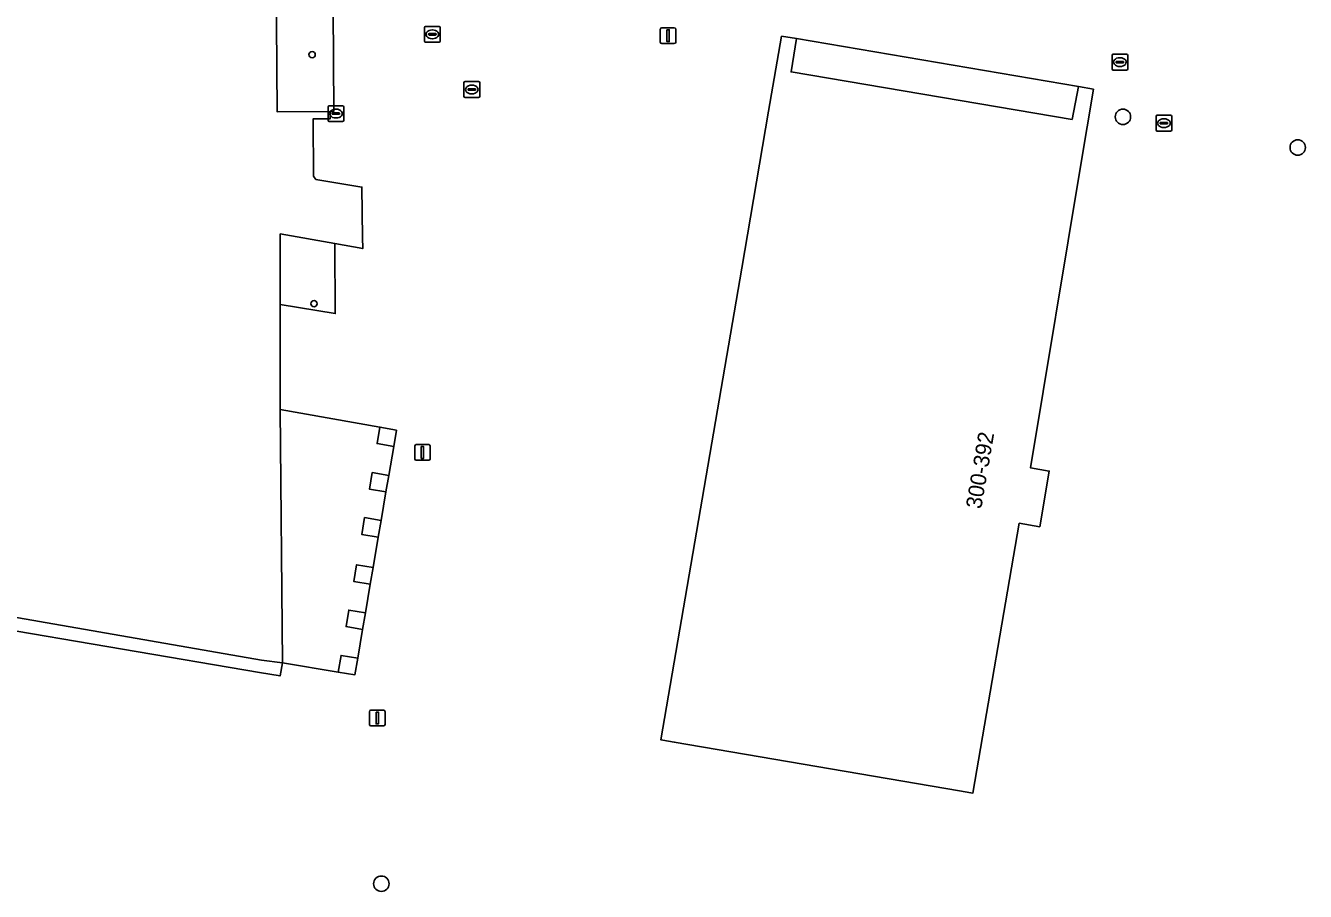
# Model space of a CAD drawing. Extents: x 161258 to 161838, y 380833 to 381727.
# Drawn here: x 161418.1 to 161499.4, y 380907.4 to 380962.4 of the extents above; entities that cross this region are included whole.
import ezdxf

# ---------------------------------------------------------------- set-up
doc = ezdxf.new("R2010")
doc.units = 0
for name, color, linetype in [('IMGEO_Boom', 7, 'Continuous'), ('IMGEO_Brandkraan', 7, 'Continuous'), ('IMGEO_Erf', 7, 'Continuous'), ('IMGEO_Kolk', 7, 'Continuous'), ('IMGEO_Lichtmast', 7, 'Continuous'), ('IMGEO_Pand', 7, 'Continuous'), ('IMGEO_Pand_nummerreeks', 7, 'Continuous'), ('IMGEO_Pand_overbouw', 7, 'Continuous'), ('IMGEO_Rioolput', 7, 'Continuous')]:
    doc.layers.add(name, color=color, linetype=linetype)

msp = doc.modelspace()

# ---------------------------------------------------------------- linework, layer by layer
at = {"layer": 'IMGEO_Boom'}
for centre in [(161487.848, 380956.64), (161498.947, 380954.694), (161440.743, 380907.913)]:
    msp.add_circle(centre, 0.489, dxfattribs=at)
at = {"layer": 'IMGEO_Brandkraan'}
for p, q in [((161437.356, 380956.423), (161437.356, 380957.275)), ((161437.431, 380957.349), (161438.283, 380957.349)), ((161437.844, 380957.129), (161437.869, 380957.129)), ((161438.357, 380957.275), (161438.357, 380956.423)), ((161438.283, 380956.349), (161437.431, 380956.349)), ((161437.615, 380956.843), (161437.615, 380956.855)), ((161438.053, 380956.806), (161437.655, 380956.806)), ((161437.658, 380956.892), (161438.056, 380956.892)), ((161437.867, 380956.569), (161437.842, 380956.569)), ((161438.099, 380956.855), (161438.099, 380956.843))]:
    msp.add_line(p, q, dxfattribs=at)
for points in [[(161437.356, 380956.423), (161437.356, 380957.275)], [(161437.431, 380957.349), (161438.283, 380957.349)], [(161438.357, 380957.275), (161438.357, 380956.423)], [(161438.283, 380956.349), (161437.431, 380956.349)]]:
    msp.add_lwpolyline(points, dxfattribs=at)
for centre, radius, start, end in [((161437.433, 380957.273), 0.0765, 91.55205, 178.44795), ((161437.433, 380957.273), 0.0765, 91.55205, 178.44795), ((161438.281, 380957.273), 0.0765, 1.55205, 88.44795), ((161438.281, 380957.273), 0.0765, 1.55205, 88.44795), ((161437.433, 380956.425), 0.0765, 181.55205, 268.44795), ((161437.433, 380956.425), 0.0765, 181.55205, 268.44795), ((161437.655, 380956.852), 0.0403, 85.87752, 175.75265), ((161437.652, 380956.842), 0.0366, 178.93798, 274.71019), ((161438.056, 380956.849), 0.043, 264.86636, 352.45326), ((161438.06, 380956.854), 0.0386, 1.73085, 96.63898), ((161438.281, 380956.425), 0.0765, 271.55205, 358.44795), ((161438.281, 380956.425), 0.0765, 271.55205, 358.44795)]:
    msp.add_arc(centre, radius, start, end, dxfattribs=at)
for centre, major_axis, ratio, start_param, end_param in [((161437.843, 380956.849), (-0.387, 0.002), 0.722429, 4.712389, 7.853982), ((161437.868, 380956.849), (-0.39, 0.002), 0.717154, 1.570796, 4.712389)]:
    msp.add_ellipse(centre, major_axis=major_axis, ratio=ratio, start_param=start_param, end_param=end_param, dxfattribs=at)
at = {"layer": 'IMGEO_Erf'}
msp.add_lwpolyline([(161434.023, 380971.148), (161434.118, 380956.967), (161437.5, 380956.974), (161437.502, 380956.514), (161436.409, 380956.509), (161436.437, 380952.87), (161436.585, 380952.666), (161439.506, 380952.173), (161439.552, 380948.973), (161439.562, 380948.274), (161437.785, 380948.589), (161434.324, 380949.202), (161434.323, 380944.725), (161434.322, 380938.038), (161434.454, 380921.951), (161433.132, 380922.125), (161415.724, 380925.137)], dxfattribs=at)
for points in [[(161467.112, 380961.61), (161466.768, 380959.497), (161484.617, 380956.479), (161485.016, 380958.571), (161485.967, 380958.39), (161485.177, 380953.62), (161481.981, 380934.334), (161483.164, 380934.132), (161482.561, 380930.592), (161481.259, 380930.814), (161478.315, 380913.67), (161478.183, 380913.693), (161477.473, 380913.814), (161459.352, 380916.915), (161458.632, 380917.038), (161458.494, 380917.062), (161463.634, 380947.032), (161464.19, 380950.274), (161465.344, 380957.003), (161466.161, 380961.765)], [(161441.705, 380936.736), (161441.53, 380935.695), (161440.475, 380935.875), (161440.653, 380936.922)], [(161441.213, 380933.859), (161441.033, 380932.805), (161439.984, 380932.983), (161440.163, 380934.037)], [(161440.732, 380930.994), (161440.548, 380929.927), (161439.495, 380930.106), (161439.676, 380931.173)], [(161440.22, 380928.004), (161440.04, 380926.947), (161438.988, 380927.125), (161439.167, 380928.182)], [(161439.733, 380925.118), (161439.554, 380924.066), (161438.498, 380924.246), (161438.677, 380925.298)], [(161439.242, 380922.245), (161439.063, 380921.191), (161438.009, 380921.364), (161438.189, 380922.424)]]:
    msp.add_lwpolyline(points, close=True, dxfattribs=at)
for centre, start, end in [((161436.347, 380960.592), 90, 270), ((161436.347, 380960.592), 270, 90), ((161436.468, 380944.767), 90, 270), ((161436.468, 380944.767), 270, 90)]:
    msp.add_arc(centre, 0.2, start, end, dxfattribs=at)
at = {"layer": 'IMGEO_Kolk'}
for p, q in [((161443.479, 380961.457), (161443.479, 380962.309)), ((161443.554, 380962.383), (161444.406, 380962.383)), ((161443.738, 380961.877), (161443.738, 380961.889)), ((161444.176, 380961.84), (161443.778, 380961.84)), ((161443.781, 380961.926), (161444.179, 380961.926)), ((161443.967, 380962.163), (161443.992, 380962.163)), ((161444.222, 380961.889), (161444.222, 380961.877)), ((161444.48, 380962.309), (161444.48, 380961.457)), ((161444.406, 380961.383), (161443.554, 380961.383)), ((161443.99, 380961.603), (161443.965, 380961.603)), ((161487.152, 380959.689), (161487.152, 380960.541)), ((161487.227, 380960.615), (161488.079, 380960.615)), ((161487.64, 380960.395), (161487.665, 380960.395)), ((161488.153, 380960.541), (161488.153, 380959.689)), ((161488.079, 380959.615), (161487.227, 380959.615)), ((161487.411, 380960.109), (161487.411, 380960.121)), ((161487.849, 380960.072), (161487.451, 380960.072)), ((161487.454, 380960.158), (161487.852, 380960.158)), ((161487.663, 380959.835), (161487.638, 380959.835)), ((161487.895, 380960.121), (161487.895, 380960.109))]:
    msp.add_line(p, q, dxfattribs=at)
for points in [[(161443.479, 380961.457), (161443.479, 380962.309)], [(161443.554, 380962.383), (161444.406, 380962.383)], [(161444.48, 380962.309), (161444.48, 380961.457)], [(161444.406, 380961.383), (161443.554, 380961.383)], [(161487.152, 380959.689), (161487.152, 380960.541)], [(161487.227, 380960.615), (161488.079, 380960.615)], [(161488.153, 380960.541), (161488.153, 380959.689)], [(161488.079, 380959.615), (161487.227, 380959.615)]]:
    msp.add_lwpolyline(points, dxfattribs=at)
for centre, radius, start, end in [((161443.556, 380962.307), 0.0765, 91.55205, 178.44795), ((161443.556, 380962.307), 0.0765, 91.55205, 178.44795), ((161443.778, 380961.886), 0.0403, 85.87752, 175.75265), ((161443.775, 380961.876), 0.0366, 178.93798, 274.71019), ((161444.179, 380961.883), 0.043, 264.86636, 352.45326), ((161444.183, 380961.888), 0.0386, 1.73085, 96.63898), ((161444.404, 380962.307), 0.0765, 1.55205, 88.44795), ((161444.404, 380962.307), 0.0765, 1.55205, 88.44795), ((161443.556, 380961.459), 0.0765, 181.55205, 268.44795), ((161443.556, 380961.459), 0.0765, 181.55205, 268.44795), ((161444.404, 380961.459), 0.0765, 271.55205, 358.44795), ((161444.404, 380961.459), 0.0765, 271.55205, 358.44795), ((161487.229, 380960.539), 0.0765, 91.55205, 178.44795), ((161487.229, 380960.539), 0.0765, 91.55205, 178.44795), ((161488.077, 380960.539), 0.0765, 1.55205, 88.44795), ((161488.077, 380960.539), 0.0765, 1.55205, 88.44795), ((161487.229, 380959.691), 0.0765, 181.55205, 268.44795), ((161487.229, 380959.691), 0.0765, 181.55205, 268.44795), ((161487.451, 380960.118), 0.0403, 85.87752, 175.75265), ((161487.448, 380960.108), 0.0366, 178.93798, 274.71019), ((161487.852, 380960.115), 0.043, 264.86636, 352.45326), ((161487.856, 380960.12), 0.0386, 1.73085, 96.63898), ((161488.077, 380959.691), 0.0765, 271.55205, 358.44795), ((161488.077, 380959.691), 0.0765, 271.55205, 358.44795)]:
    msp.add_arc(centre, radius, start, end, dxfattribs=at)
for centre, major_axis, ratio, start_param, end_param in [((161443.966, 380961.883), (-0.387, 0.002), 0.722429, 4.712389, 7.853982), ((161443.991, 380961.883), (-0.39, 0.002), 0.717154, 1.570796, 4.712389), ((161487.639, 380960.115), (-0.387, 0.002), 0.722429, 4.712389, 7.853982), ((161487.664, 380960.115), (-0.39, 0.002), 0.717154, 1.570796, 4.712389)]:
    msp.add_ellipse(centre, major_axis=major_axis, ratio=ratio, start_param=start_param, end_param=end_param, dxfattribs=at)
at = {"layer": 'IMGEO_Lichtmast'}
for p, q in [((161458.456, 380961.395), (161458.456, 380962.195)), ((161458.456, 380962.195), (161458.456, 380961.395)), ((161458.556, 380962.295), (161459.346, 380962.295)), ((161459.346, 380962.295), (161458.556, 380962.295)), ((161459.446, 380962.195), (161459.446, 380961.395)), ((161459.446, 380961.395), (161459.446, 380962.195)), ((161459.346, 380961.295), (161458.556, 380961.295)), ((161458.556, 380961.295), (161459.346, 380961.295)), ((161442.959, 380935.815), (161443.749, 380935.815)), ((161443.749, 380935.815), (161442.959, 380935.815)), ((161442.859, 380934.915), (161442.859, 380935.715)), ((161442.859, 380935.715), (161442.859, 380934.915)), ((161443.849, 380935.715), (161443.849, 380934.915)), ((161443.849, 380934.915), (161443.849, 380935.715)), ((161443.749, 380934.815), (161442.959, 380934.815)), ((161442.959, 380934.815), (161443.749, 380934.815)), ((161439.985, 380918.039), (161439.985, 380918.839)), ((161439.985, 380918.839), (161439.985, 380918.039)), ((161440.085, 380918.939), (161440.875, 380918.939)), ((161440.875, 380918.939), (161440.085, 380918.939)), ((161440.975, 380918.839), (161440.975, 380918.039)), ((161440.975, 380918.039), (161440.975, 380918.839)), ((161440.875, 380917.939), (161440.085, 380917.939)), ((161440.085, 380917.939), (161440.875, 380917.939))]:
    msp.add_line(p, q, dxfattribs=at)
for points in [[(161458.876, 380962.17), (161459.026, 380962.17), (161459.026, 380961.42), (161458.876, 380961.42), (161458.876, 380962.17)], [(161443.279, 380935.69), (161443.429, 380935.69), (161443.429, 380934.94), (161443.279, 380934.94), (161443.279, 380935.69)], [(161440.405, 380918.814), (161440.555, 380918.814), (161440.555, 380918.064), (161440.405, 380918.064), (161440.405, 380918.814)]]:
    msp.add_lwpolyline(points, dxfattribs=at)
for centre, start, end in [((161458.556, 380962.195), 90, 180), ((161458.556, 380962.195), 90, 180), ((161459.346, 380962.195), 0, 90), ((161459.346, 380962.195), 360, 90), ((161458.556, 380961.395), 180, 270), ((161458.556, 380961.395), 180, 270), ((161459.346, 380961.395), 270, 0), ((161459.346, 380961.395), 270, 0), ((161442.959, 380935.715), 90, 180), ((161442.959, 380935.715), 90, 180), ((161443.749, 380935.715), 0, 90), ((161443.749, 380935.715), 360, 90), ((161442.959, 380934.915), 180, 270), ((161442.959, 380934.915), 180, 270), ((161443.749, 380934.915), 270, 0), ((161443.749, 380934.915), 270, 0), ((161440.085, 380918.839), 90, 180), ((161440.085, 380918.839), 90, 180), ((161440.875, 380918.839), 0, 90), ((161440.875, 380918.839), 360, 90), ((161440.085, 380918.039), 180, 270), ((161440.085, 380918.039), 180, 270), ((161440.875, 380918.039), 270, 0), ((161440.875, 380918.039), 270, 0)]:
    msp.add_arc(centre, 0.1, start, end, dxfattribs=at)
at = {"layer": 'IMGEO_Pand'}
msp.add_lwpolyline([(161415.724, 380925.137), (161433.132, 380922.125), (161434.454, 380921.951), (161434.322, 380938.038), (161434.323, 380944.725), (161434.324, 380949.202), (161437.785, 380948.589), (161439.562, 380948.274), (161439.552, 380948.973), (161439.506, 380952.173), (161436.585, 380952.666), (161436.437, 380952.87), (161436.409, 380956.509), (161437.502, 380956.514), (161437.5, 380956.974), (161434.118, 380956.967), (161434.023, 380971.148)], dxfattribs=at)
for points in [[(161467.112, 380961.61), (161466.161, 380961.765), (161465.344, 380957.003), (161464.19, 380950.274), (161463.634, 380947.032), (161458.494, 380917.062), (161458.632, 380917.038), (161459.352, 380916.915), (161477.473, 380913.814), (161478.183, 380913.693), (161478.315, 380913.67), (161481.259, 380930.814), (161482.561, 380930.592), (161483.164, 380934.132), (161481.981, 380934.334), (161485.177, 380953.62), (161485.967, 380958.39), (161485.016, 380958.571), (161484.617, 380956.479), (161466.768, 380959.497)], [(161441.705, 380936.736), (161440.653, 380936.922), (161440.475, 380935.875), (161441.53, 380935.695)], [(161441.213, 380933.859), (161440.163, 380934.037), (161439.984, 380932.983), (161441.033, 380932.805)], [(161440.732, 380930.994), (161439.676, 380931.173), (161439.495, 380930.106), (161440.548, 380929.927)], [(161440.22, 380928.004), (161439.167, 380928.182), (161438.988, 380927.125), (161440.04, 380926.947)], [(161439.733, 380925.118), (161438.677, 380925.298), (161438.498, 380924.246), (161439.554, 380924.066)], [(161439.242, 380922.245), (161438.189, 380922.424), (161438.009, 380921.364), (161439.063, 380921.191)]]:
    msp.add_lwpolyline(points, close=True, dxfattribs=at)
for centre, start, end in [((161436.347, 380960.592), 90, 270), ((161436.347, 380960.592), 270, 90), ((161436.468, 380944.767), 90, 270), ((161436.468, 380944.767), 270, 90)]:
    msp.add_arc(centre, 0.2, start, end, dxfattribs=at)
at = {"layer": 'IMGEO_Pand_overbouw'}
for points in [[(161437.727, 380956.976), (161437.591, 380976.498), (161436.265, 380976.719), (161436.226, 380976.726), (161433.514, 380977.179), (161432.521, 380971.424), (161434.023, 380971.148), (161434.118, 380956.967)], [(161467.112, 380961.61), (161466.768, 380959.497), (161484.617, 380956.479), (161485.016, 380958.571)], [(161437.785, 380948.589), (161434.324, 380949.202), (161434.323, 380944.725), (161437.816, 380944.144)], [(161440.653, 380936.922), (161434.322, 380938.038), (161434.454, 380921.951), (161438.009, 380921.364), (161438.189, 380922.424), (161439.242, 380922.245), (161439.554, 380924.066), (161438.498, 380924.246), (161438.677, 380925.298), (161439.733, 380925.118), (161440.04, 380926.947), (161438.988, 380927.125), (161439.167, 380928.182), (161440.22, 380928.004), (161440.548, 380929.927), (161439.495, 380930.106), (161439.676, 380931.173), (161440.732, 380930.994), (161441.033, 380932.805), (161439.984, 380932.983), (161440.163, 380934.037), (161441.213, 380933.859), (161441.53, 380935.695), (161440.475, 380935.875)], [(161396.713, 380927.503), (161415.584, 380924.3), (161432.997, 380921.344), (161434.313, 380921.12), (161434.454, 380921.951), (161433.132, 380922.125), (161415.724, 380925.137), (161396.856, 380928.346)]]:
    msp.add_lwpolyline(points, close=True, dxfattribs=at)
at = {"layer": 'IMGEO_Rioolput'}
for p, q in [((161445.988, 380957.951), (161445.988, 380958.803)), ((161446.063, 380958.877), (161446.915, 380958.877)), ((161446.476, 380958.657), (161446.501, 380958.657)), ((161446.989, 380958.803), (161446.989, 380957.951)), ((161446.915, 380957.877), (161446.063, 380957.877)), ((161446.247, 380958.371), (161446.247, 380958.383)), ((161446.685, 380958.334), (161446.287, 380958.334)), ((161446.29, 380958.42), (161446.688, 380958.42)), ((161446.499, 380958.097), (161446.474, 380958.097)), ((161446.731, 380958.383), (161446.731, 380958.371)), ((161489.948, 380955.812), (161489.948, 380956.664)), ((161490.023, 380956.738), (161490.875, 380956.738)), ((161490.207, 380956.232), (161490.207, 380956.244)), ((161490.645, 380956.195), (161490.247, 380956.195)), ((161490.25, 380956.281), (161490.648, 380956.281)), ((161490.436, 380956.518), (161490.461, 380956.518)), ((161490.691, 380956.244), (161490.691, 380956.232)), ((161490.949, 380956.664), (161490.949, 380955.812)), ((161490.875, 380955.738), (161490.023, 380955.738)), ((161490.459, 380955.958), (161490.434, 380955.958))]:
    msp.add_line(p, q, dxfattribs=at)
for points in [[(161445.988, 380957.951), (161445.988, 380958.803)], [(161446.063, 380958.877), (161446.915, 380958.877)], [(161446.989, 380958.803), (161446.989, 380957.951)], [(161446.915, 380957.877), (161446.063, 380957.877)], [(161489.948, 380955.812), (161489.948, 380956.664)], [(161490.023, 380956.738), (161490.875, 380956.738)], [(161490.949, 380956.664), (161490.949, 380955.812)], [(161490.875, 380955.738), (161490.023, 380955.738)]]:
    msp.add_lwpolyline(points, dxfattribs=at)
for centre, radius, start, end in [((161446.065, 380958.801), 0.0765, 91.55205, 178.44795), ((161446.065, 380958.801), 0.0765, 91.55205, 178.44795), ((161446.913, 380958.801), 0.0765, 1.55205, 88.44795), ((161446.913, 380958.801), 0.0765, 1.55205, 88.44795), ((161446.065, 380957.953), 0.0765, 181.55205, 268.44795), ((161446.065, 380957.953), 0.0765, 181.55205, 268.44795), ((161446.287, 380958.38), 0.0403, 85.87752, 175.75265), ((161446.284, 380958.37), 0.0366, 178.93798, 274.71019), ((161446.688, 380958.377), 0.043, 264.86636, 352.45326), ((161446.692, 380958.382), 0.0386, 1.73085, 96.63898), ((161446.913, 380957.953), 0.0765, 271.55205, 358.44795), ((161446.913, 380957.953), 0.0765, 271.55205, 358.44795), ((161490.025, 380956.662), 0.0765, 91.55205, 178.44795), ((161490.025, 380956.662), 0.0765, 91.55205, 178.44795), ((161490.247, 380956.241), 0.0403, 85.87752, 175.75265), ((161490.244, 380956.231), 0.0366, 178.93798, 274.71019), ((161490.648, 380956.238), 0.043, 264.86636, 352.45326), ((161490.652, 380956.243), 0.0386, 1.73085, 96.63898), ((161490.873, 380956.662), 0.0765, 1.55205, 88.44795), ((161490.873, 380956.662), 0.0765, 1.55205, 88.44795), ((161490.025, 380955.814), 0.0765, 181.55205, 268.44795), ((161490.025, 380955.814), 0.0765, 181.55205, 268.44795), ((161490.873, 380955.814), 0.0765, 271.55205, 358.44795), ((161490.873, 380955.814), 0.0765, 271.55205, 358.44795)]:
    msp.add_arc(centre, radius, start, end, dxfattribs=at)
for centre, major_axis, ratio, start_param, end_param in [((161446.475, 380958.377), (-0.387, 0.002), 0.722429, 4.712389, 7.853982), ((161446.5, 380958.377), (-0.39, 0.002), 0.717154, 1.570796, 4.712389), ((161490.435, 380956.238), (-0.387, 0.002), 0.722429, 4.712389, 7.853982), ((161490.46, 380956.238), (-0.39, 0.002), 0.717154, 1.570796, 4.712389)]:
    msp.add_ellipse(centre, major_axis=major_axis, ratio=ratio, start_param=start_param, end_param=end_param, dxfattribs=at)

# ---------------------------------------------------------------- texts
at = {"layer": 'IMGEO_Pand_nummerreeks'}
msp.add_text('300-392', height=1, rotation=80.27572, dxfattribs=at).set_placement((161478.845, 380931.686))

doc.saveas('drawing.dxf')
